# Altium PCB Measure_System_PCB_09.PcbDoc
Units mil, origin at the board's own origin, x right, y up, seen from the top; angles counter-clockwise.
Board outline 6000 x 4000 mil, 2 copper layers (Top Layer, Bottom Layer); 44 components, 29 nets, 115 pads, 0 vias.
Unrouted connection lines stored in the file: 2.
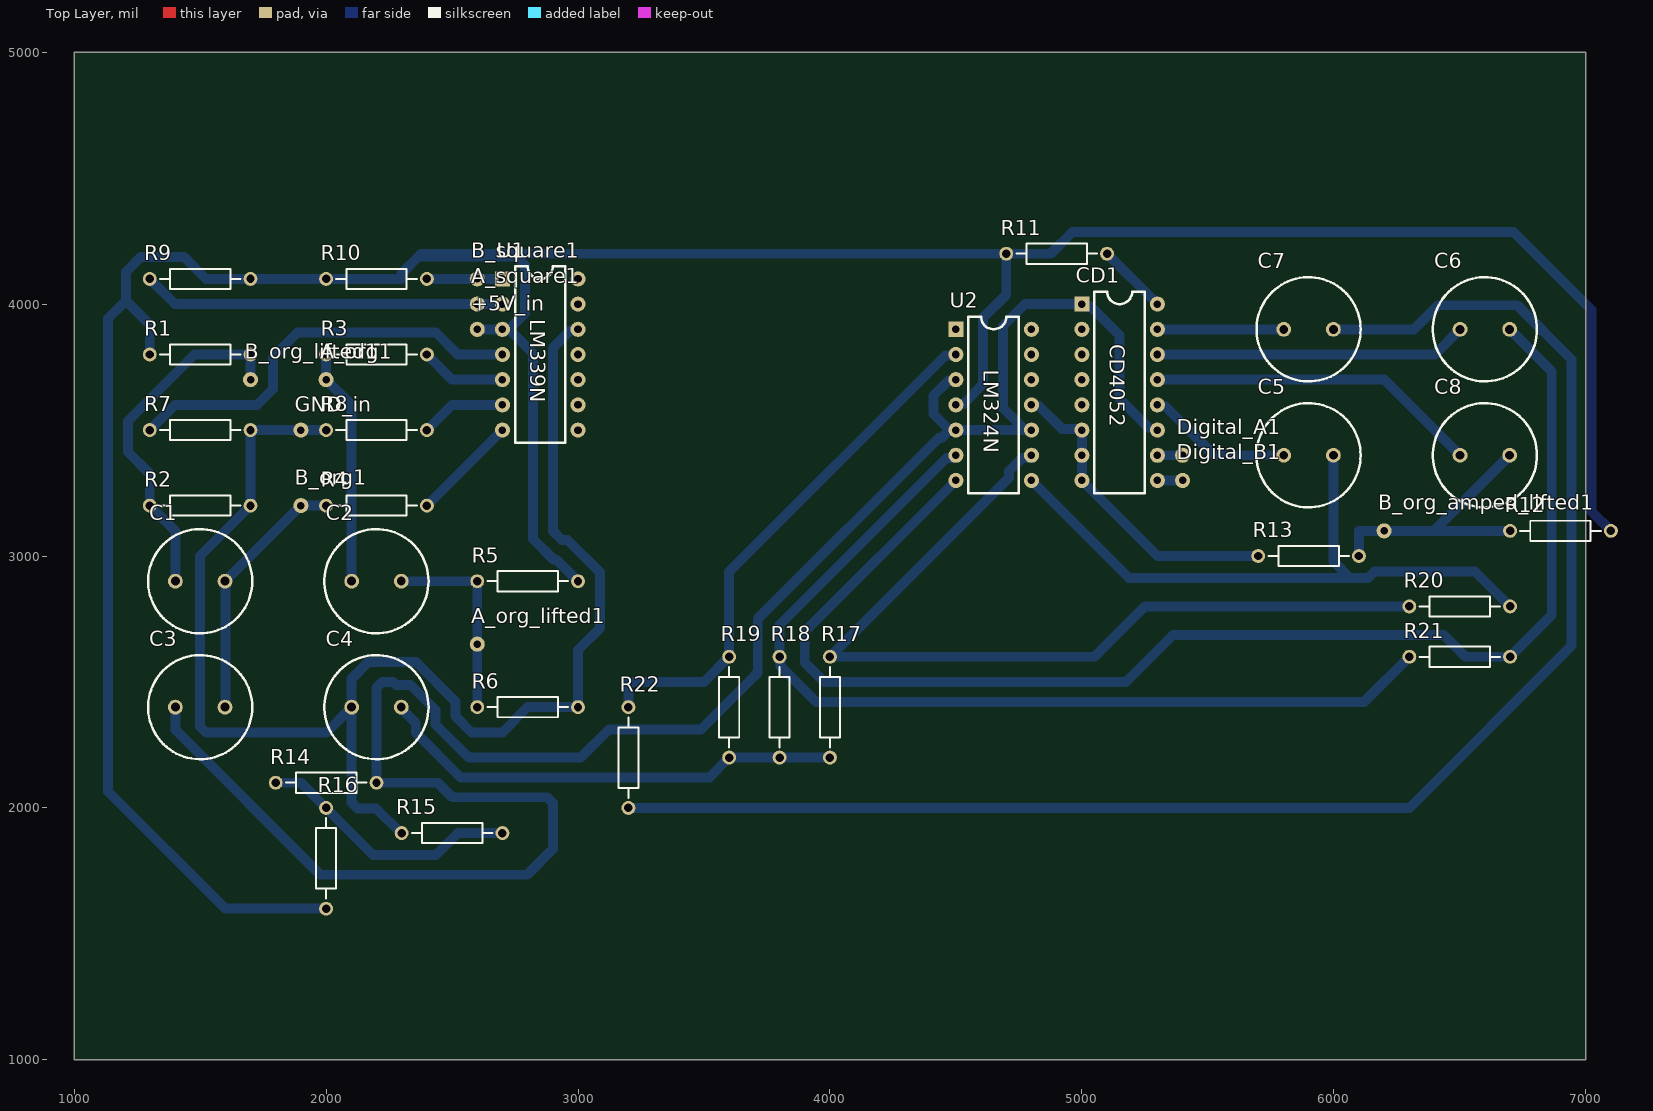
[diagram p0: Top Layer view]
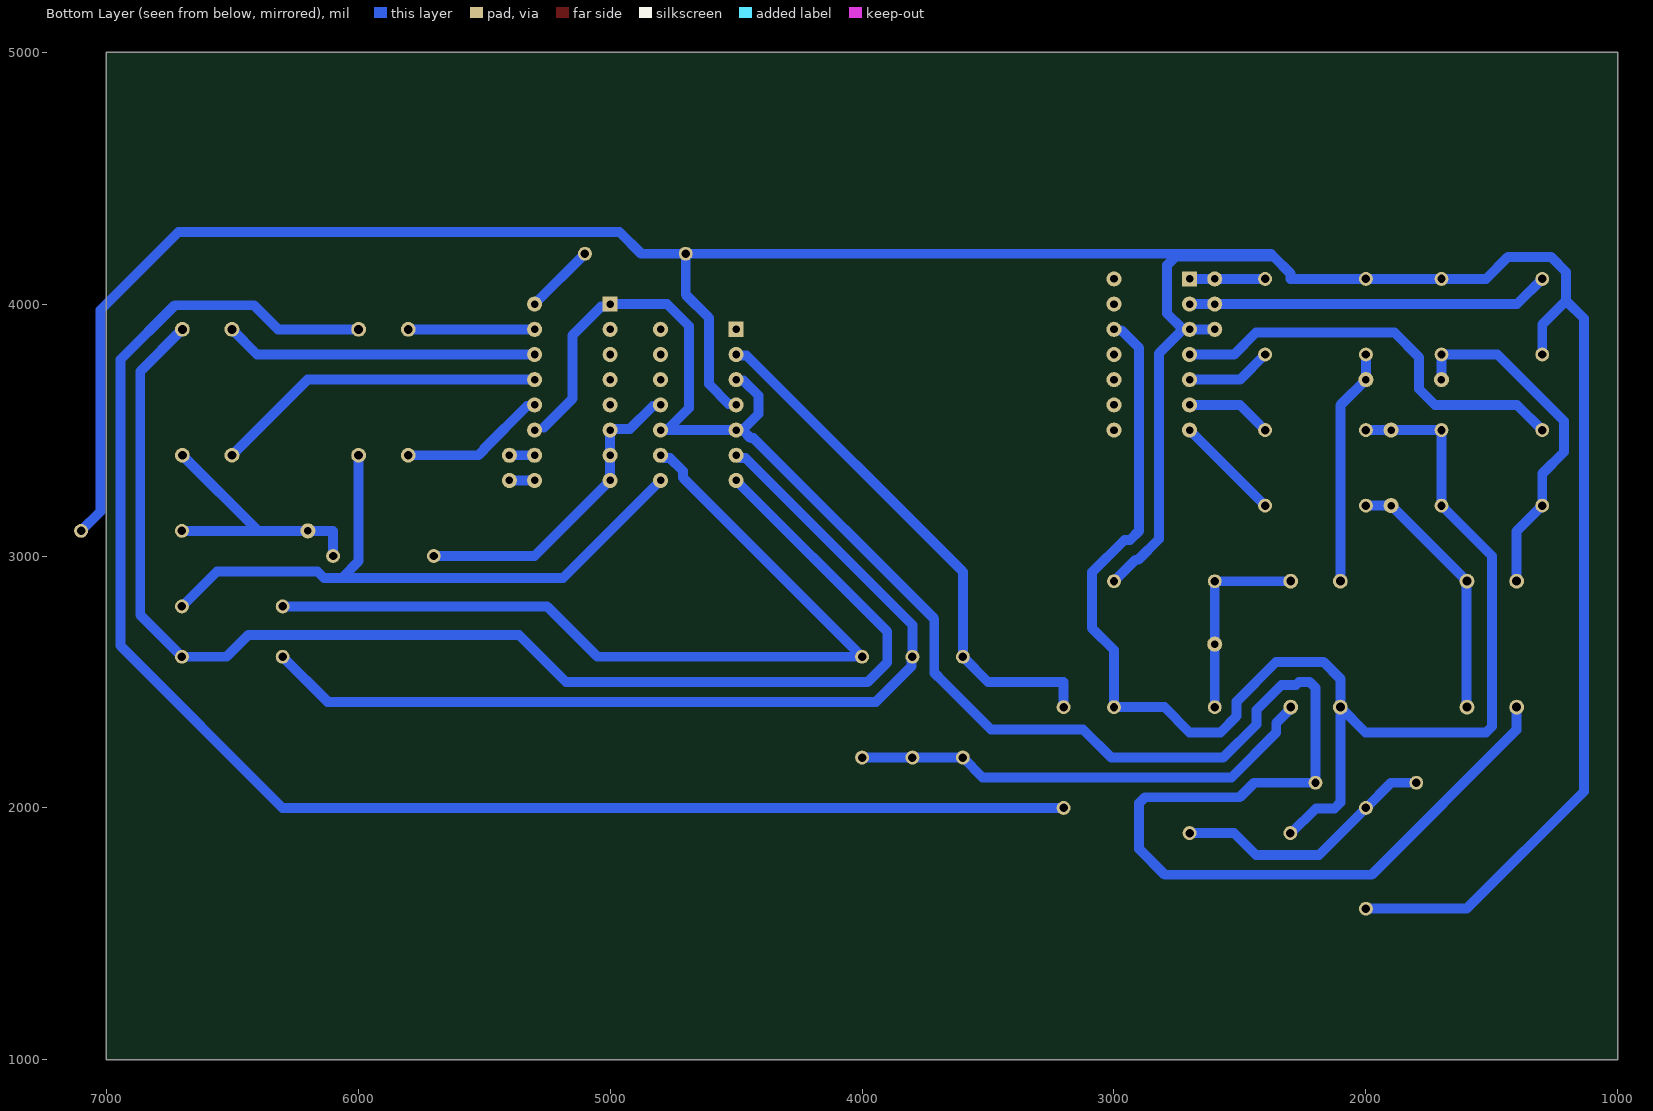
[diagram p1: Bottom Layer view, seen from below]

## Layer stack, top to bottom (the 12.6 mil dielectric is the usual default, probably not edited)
Top Solder: solder mask 0.4, Solder Resist, Dk 3.5
Top Layer: signal copper 1.4
Dielectric 1: dielectric 12.6, FR-4, Dk 4.8
Bottom Layer: signal copper 1.4
Bottom Solder: solder mask 0.4, Solder Resist, Dk 3.5

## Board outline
1000,1000 7000,1000 7000,5000 1000,5000

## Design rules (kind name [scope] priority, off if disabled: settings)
Clearance [All] p1: gap=39.37 ignorepadtopadclearanceinfootprint=FALSE
PolygonConnect [All] p1: connectstyle=Relief reliefconductorwidth=10 reliefentries=4 polygonreliefangle="90 Angle" airgapwidth=10
RoutingLayers [All] p1: top layer_v5=FALSE bottom layer_v5=TRUE
RoutingVias [All] p1: holewidth=28 width=50 viastyle="Through Hole" minholewidth=28 minwidth=50 maxholewidth=28 maxwidth=50
SolderMaskExpansion [All] p1: expansion=4 istentingtop=FALSE
Width [All] p1: maxlimit=393.7 minlimit=19.68 preferedwidth=39.37 toplayer_maxwidth=393.7 bottomlayer_prefwidth=39.37 minimp=50.000000 maximp=50.000000 favimp=50.000000
29 further rules are at their usual default settings.

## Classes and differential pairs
component class Part_Square: C1 C2 R1 R2 R3 R4 R5 R6 R7 R8 R9 R10 U1
component class Part_PGA: C3 C4 C5 C7 CD1 R11 R12 R13 R14 R16 R17 R18 R19 R20 R21 R22 U2
component class Measure_System_Main: +5V_in A_org1 A_square1 B_org1 B_org_amped_lifted1 B_org_lifted1 B_square1 Digital_A1 Digital_B1 GND_in

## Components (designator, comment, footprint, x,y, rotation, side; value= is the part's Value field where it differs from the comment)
+5V_in "Hole" Hole 2600,3900 r90 top
A_org1 "Hole" Hole 2000,3700 r90 top
A_org_lifted1 "Hole" Hole 2600,2650 r90 top
A_square1 "Hole" Hole 2600,4000 r90 top
B_org1 "Hole" Hole 1900,3200 r90 top
B_org_amped_lifted1 "Hole" Hole 6200,3100 r90 top
B_org_lifted1 "Hole" Hole 1700,3700 r90 top
B_square1 "Hole" Hole 2600,4100 r90 top
C1 "Cap Pol1" RB5-10.5 1500,2900 r180 top value=10u
C2 "Cap Pol1" RB5-10.5 2200,2900 r0 top value=10u
C3 "Cap Pol1" RB5-10.5 1500,2400 r180 top value=10u
C4 "Cap Pol1" RB5-10.5 2200,2400 r0 top value=10u
C5 "Cap Pol1" RB5-10.5 5900,3400 r180 top value=10u
C6 "Cap Pol1" RB5-10.5 6600,3900 r180 top value=10u
C7 "Cap Pol1" RB5-10.5 5900,3900 r180 top value=10u
C8 "Cap Pol1" RB5-10.5 6600,3400 r0 top value=10u
CD1 "CD4052" CD4052 5000,4000 r0 top
Digital_A1 "Hole" Hole 5400,3400 r270 top
Digital_B1 "Hole" Hole 5400,3300 r270 top
GND_in "Hole" Hole 1900,3500 r90 top
R1 "Res2" AXIAL-0.4 1500,3800 r180 top value=100k
R2 "Res2" AXIAL-0.4 1500,3200 r180 top value=100k
R3 "Res2" AXIAL-0.4 2200,3800 r180 top value=1k
R4 "Res2" AXIAL-0.4 2200,3200 r180 top value=1k
R5 "Res2" AXIAL-0.4 2800,2900 r0 top value=100k
R6 "Res2" AXIAL-0.4 2800,2400 r180 top value=100k
R7 "Res2" AXIAL-0.4 1500,3500 r180 top value=10k
R8 "Res2" AXIAL-0.4 2200,3500 r180 top value=10k
R9 "Res2" AXIAL-0.4 1500,4100 r180 top value=10k
R10 "Res2" AXIAL-0.4 2200,4100 r180 top value=10k
R11 "Res2" AXIAL-0.4 4900,4200 r180 top value=200
R12 "Res2" AXIAL-0.4 6900,3100 r0 top value=100k
R13 "Res2" AXIAL-0.4 5900,3000 r0 top value=100k
R14 "Res2" AXIAL-0.4 2000,2100 r0 top value=100k
R15 "Res2" AXIAL-0.4 2500,1900 r0 top value=100k
R16 "Res2" AXIAL-0.4 2000,1800 r90 top value=100k
R17 "Res2" AXIAL-0.4 4000,2400 r90 top value=50k
R18 "Res2" AXIAL-0.4 3800,2400 r90 top value=24k
R19 "Res2" AXIAL-0.4 3600,2400 r90 top value=12k
R20 "Res2" AXIAL-0.4 6500,2800 r0 top value=100k
R21 "Res2" AXIAL-0.4 6500,2600 r0 top value=100k
R22 "Res2" AXIAL-0.4 3200,2200 r270 top value=100k
U1 "LM339N" LM339N 2700,4100 r0 top
U2 "LM324N" LM324N 4500,3900 r0 top

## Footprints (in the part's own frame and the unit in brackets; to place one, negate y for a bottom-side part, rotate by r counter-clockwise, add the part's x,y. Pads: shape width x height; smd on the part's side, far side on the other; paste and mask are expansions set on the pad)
AXIAL-0.4 [mm] "Axial Device, Thru-Hole; 2 Leads; 0.4 in Pin Spacing"
  round 1.4 hole 0.85: 1(-5.08,0) 2(5.08,0)
  silkscreen extent -4.06,-1.02 4.06,1.02
CD4052 [mil]
  rect 60x60 hole 30: 1(0,0)
  round 60 hole 30 mask+4: 2(0,-100) 3(0,-200) 4(0,-300) 5(0,-400) 6(0,-500) 7(0,-600) 8(0,-700) 9(300,-700) 10(300,-600) 11(300,-500) 12(300,-400) 13(300,-300) 14(300,-200) 15(300,-100) 16(300,0)
  silkscreen extent 50,-750 250,50
Hole [mil]
  round 60 hole 30 mask+4: 1(0,0)
LM324N [mil]
  rect 60x60 hole 30: 1(0,0)
  round 60 hole 30 mask+4: 2(0,-100) 3(0,-200) 4(0,-300) 5(0,-400) 6(0,-500) 7(0,-600) 8(300,-600) 9(300,-500) 10(300,-400) 11(300,-300) 12(300,-200) 13(300,-100) 14(300,0)
  silkscreen extent 50,-650 250,50
LM339N [mil]
  rect 60x60 hole 30: 1(0,0)
  round 60 hole 30 mask+4: 2(0,-100) 3(0,-200) 4(0,-300) 5(0,-400) 6(0,-500) 7(0,-600) 8(300,-600) 9(300,-500) 10(300,-400) 11(300,-300) 12(300,-200) 13(300,-100) 14(300,0)
  silkscreen extent 50,-650 250,50
RB5-10.5 [mm] "Capacitor (Radial); 2 Leads"
  round 1.5 hole 0.9: 1(-2.5,0) 2(2.5,0)
  silkscreen extent -5.25,-5.25 5.25,5.25

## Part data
C1 C2 C3 C4 C5 C6 C7 C8: "Polarized Capacitor (Radial)"
R1 R2 R3 R4 R5 R6 R7 R8 R9 R10 R11 R12 R13 R14 R15 R16 R17 R18 R19 R20 R21 R22: "Resistor"

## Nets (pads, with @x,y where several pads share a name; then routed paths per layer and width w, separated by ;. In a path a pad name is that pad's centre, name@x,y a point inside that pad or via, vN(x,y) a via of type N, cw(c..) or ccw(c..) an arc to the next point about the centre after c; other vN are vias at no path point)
+5: +5V_in.1 R1.2 R5.2 R9.1 R10.2 R11.2 R12.2 R16.1 U1.3 U2.4 | length 13069.6
  Bottom Layer w39.37: R1.2 1300,3918.44 1205.06,4013.38 ; R16.1 1600,1600 1134.65,2065.35 1134.65,3942.96 1205.06,4013.38 ; +5V_in.1 U1.3 2703.95,3903.95 2729.89,3903.95 2789.06,3963.11 2789.06,4154.46 2754.46,4189.06 2366.56,4189.06 ; 2729.89,3896.05 2821.26,3804.68 2821.26,3067.38 2903.45,2985.2 2914.8,2985.2 R5.2 ; U2.4@4496.05,3603.95 U2.4 4503.95,3603.95 4529.89,3603.95 4608.29,3682.35 4608.29,3945.59 4700,4037.3 R11.2 ; R12.2 7022.83,3177.17 7022.83,3977.17 6713.39,4286.61 4963.38,4286.61 4876.76,4200 R11.2 ; 1205.06,4013.38 1205.06,4127.55 1264.12,4186.61 1436.62,4186.61 1523.24,4100 R9.1 R10.2 2300,4100 2300,4122.49 2366.56,4189.06 ; 2366.56,4189.06 2377.51,4200 2754.46,4200 R11.2
B_org: B_org1.1 C1.1 C3.1 R4.2 | length 1026.5
  Bottom Layer w39.37: C3.1@1600,2400 1600,2898.43 C1.1 1599.21,2900 1899.21,3200 B_org1.1 R4.2
B_org_amp_1: C3.2 CD1.1 CD1.11 R14.2 U2.3 U2.5 U2.10 | length 8273.6
  Bottom Layer w39.37: C3.2 1401.57,2310.13 1977.06,1734.65 2798.2,1734.65 2900,1836.45 2900,2019.46 2876.94,2042.52 2500.92,2042.52 2443.44,2100 R14.2 2200,2476.94 2223.06,2500 2266.15,2500 2277.57,2488.58 2335.12,2488.58 2434.65,2389.05 2434.65,2331.51 2566.15,2200 3010.94,2200 3122.8,2311.86 3488.79,2311.86 3676.94,2500 3713.39,2536.45 3713.39,2750.68 4430.5,3467.8 4441.85,3467.8 4470.11,3496.05 ; U2.3 4496.05,3696.05 4470.11,3696.05 4410.94,3636.89 4410.94,3563.11 4470.11,3503.95 4496.05,3503.95 U2.5 U2.10@4770.11,3500 ; U2.10 4796.05,3503.95 4770.11,3503.95 4687.03,3587.03 4687.03,3912.97 4774.06,4000 CD1.1 5010.31,3989.68 5036.26,3989.68 5149.69,3876.26 5149.69,3624.37 5263.11,3510.94
B_org_amp_2.5: C5.2 CD1.12 | length 586.1
  Bottom Layer w39.37: CD1.12 5303.95,3596.05 5329.89,3596.05 5500,3425.94 5500,3423.06 5523.06,3400 C5.2
B_org_amp_5: C6.2 CD1.14 | length 1243
  Bottom Layer w39.37: CD1.14 6401.57,3800 C6.2
B_org_amp_10: C7.2 CD1.15 | length 501.6
  Bottom Layer w39.37: CD1.15 C7.2
B_org_amped: C8.1 CD1.13 | length 1325.8
  Bottom Layer w39.37: CD1.13 6201.57,3700 C8.1
Digital_A: CD1.10 Digital_A1.1 | length 100
  Bottom Layer w39.37: CD1.10 Digital_A1.1
Digital_B: CD1.9 Digital_B1.1 | length 100
  Bottom Layer w39.37: CD1.9 Digital_B1.1
GND: C4.1 CD1.6 CD1.7 CD1.8 GND_in.1 R2.1 R6.1 R7.1 R8.2 R13.1 R15.1 U1.12 U2.11 | length 7017.4
  Bottom Layer w39.37: R8.2 GND_in.1 R7.1 R2.1 1500,3000 1500,2323.06 1523.06,2300 2001.57,2300 C4.1 ; R15.1 2296.85,1900 2198.43,1998.43 2124.64,1998.43 2101.57,2021.49 C4.1 ; U1.12 2996.05,3896.05 2970.11,3896.05 2900,3825.94 2900,3100 2936.06,3063.94 2958.55,3063.94 3086.61,2935.88 3086.61,2713.38 3000,2626.76 R6.1 2800,2400 2700,2300 2577.51,2300 2513.39,2364.12 2513.39,2421.67 2356.32,2578.74 2167.38,2578.74 2101.57,2512.93 C4.1 ; U2.11 4803.95,3596.05 4829.89,3596.05 4922,3503.95 4996.05,3503.95 CD1.6 CD1.7 CD1.8 5300,3000 R13.1
NetA_org1_1: A_org1.1 C2.1 R3.2 | length 942.1
  Bottom Layer w39.37: R3.2 A_org1.1 2101.57,3598.43 C2.1
NetA_org_lifted1_1: A_org_lifted1.1 C2.2 R5.1 R6.2 | length 801.6
  Bottom Layer w39.37: C2.2 R5.1 R6.2
NetA_square1_1: A_square1.1 R9.2 U1.2 | length 1441.4
  Bottom Layer w39.37: R9.2 1400,4000 A_square1.1 U1.2
NetB_org_amped_lifted1_1: B_org_amped_lifted1.1 C8.2 R12.1 R13.2 | length 1125.8
  Bottom Layer w39.37: R13.2 6100,3100 B_org_amped_lifted1.1 6398.43,3100 ; R12.1 6398.43,3100 ; C8.2@6700,3400 C8.2 6398.43,3100
NetB_org_lifted1_1: B_org_lifted1.1 C1.2 R1.1 R2.2 | length 1409.8
  Bottom Layer w39.37: C1.2 1401.57,3098.43 R2.2 1300,3326.76 1213.39,3413.38 1213.39,3535.88 1477.51,3800 R1.1 B_org_lifted1.1
NetB_square1_1: B_square1.1 R10.1 U1.1 | length 300
  Bottom Layer w39.37: R10.1 B_square1.1 U1.1
NetC4_2: C4.2 R17.1 R18.1 R19.1 | length 1875.2
  Bottom Layer w39.37: C4.2 2298.43,2394.67 2355.91,2337.19 2355.91,2298.89 2533.54,2121.26 3521.26,2121.26 R19.1 R18.1 R17.1
NetC5_1: C5.1 R20.2 U2.8 | length 2642.3
  Bottom Layer w39.37: U2.8 5186.61,2913.39 6064.12,2913.39 ; C5.1 5998.43,2979.08 6064.12,2913.39 ; R20.2 6560.83,2939.17 6161.66,2939.17 6135.88,2913.39 6064.12,2913.39
NetC6_1: C6.1 R21.2 U2.7 | length 5353.9
  Bottom Layer w39.37: U2.7 3900,2700 3900,2577.51 3977.51,2500 5175,2500 5361.62,2686.61 6436.62,2686.61 6523.24,2600 R21.2 6865.35,2765.35 6865.35,3733.07 C6.1
NetC7_1: C7.1 R22.2 U2.1 | length 6221.1
  Bottom Layer w39.37: R22.2 6300,2000 6944.09,2644.09 6944.09,3779.61 6728.16,3995.54 6413.73,3995.54 6318.18,3900 C7.1
NetCD1_16: CD1.16 R11.1 | length 282.8
  Bottom Layer w39.37: R11.1 CD1.16
NetR3_1: R3.1 U1.5 | length 341.4
  Bottom Layer w39.37: R3.1 2500,3700 U1.5
NetR4_1: R4.1 U1.7 | length 424.3
  Bottom Layer w39.37: R4.1 U1.7
NetR7_2: R7.2 U1.4 | length 1669.8
  Bottom Layer w39.37: R7.2 1400,3600 1725.94,3600 1789.06,3663.11 1789.06,3789.06 1886.61,3886.61 2435.88,3886.61 2522.49,3800 U1.4
NetR8_1: R8.1 U1.6 | length 341.4
  Bottom Layer w39.37: R8.1 2500,3600 U1.6
NetR14_1: R14.1 R15.2 R16.2 | length 1054.6
  Bottom Layer w39.37: R14.1 1900,2100 R16.2 2186.61,1813.39 2436.62,1813.39 2523.24,1900 R15.2
NetR17_2: R17.2 R20.1 U2.9 | length 3529.4
  Bottom Layer w39.37: U2.9 4794.42,3400 4783.47,3389.06 4763.11,3389.06 4710.94,3336.89 4710.94,3310.94 R17.2 5050,2600 5250,2800 R20.1
NetR18_2: R18.2 R21.1 U2.6 | length 3773
  Bottom Layer w39.37: U2.6 4494.42,3400 4483.47,3389.06 4463.11,3389.06 3800,2725.94 R18.2 3803.01,2596.99 3803.01,2563.14 3944.89,2421.26 6121.26,2421.26 R21.1
NetR19_2: R19.2 R22.1 U2.2 | length 2136.1
  Bottom Layer w39.37: R22.1 3200,2500 3500,2500 R19.2 3600,2937.3 4458.75,3796.05 4496.05,3796.05 U2.2
pads on no net: CD1.2 CD1.3 CD1.4 CD1.5 U1.8 U1.9 U1.10 U1.11 U1.13 U1.14 U2.12 U2.13 U2.14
